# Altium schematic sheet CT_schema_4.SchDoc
size 280 x 211 mm
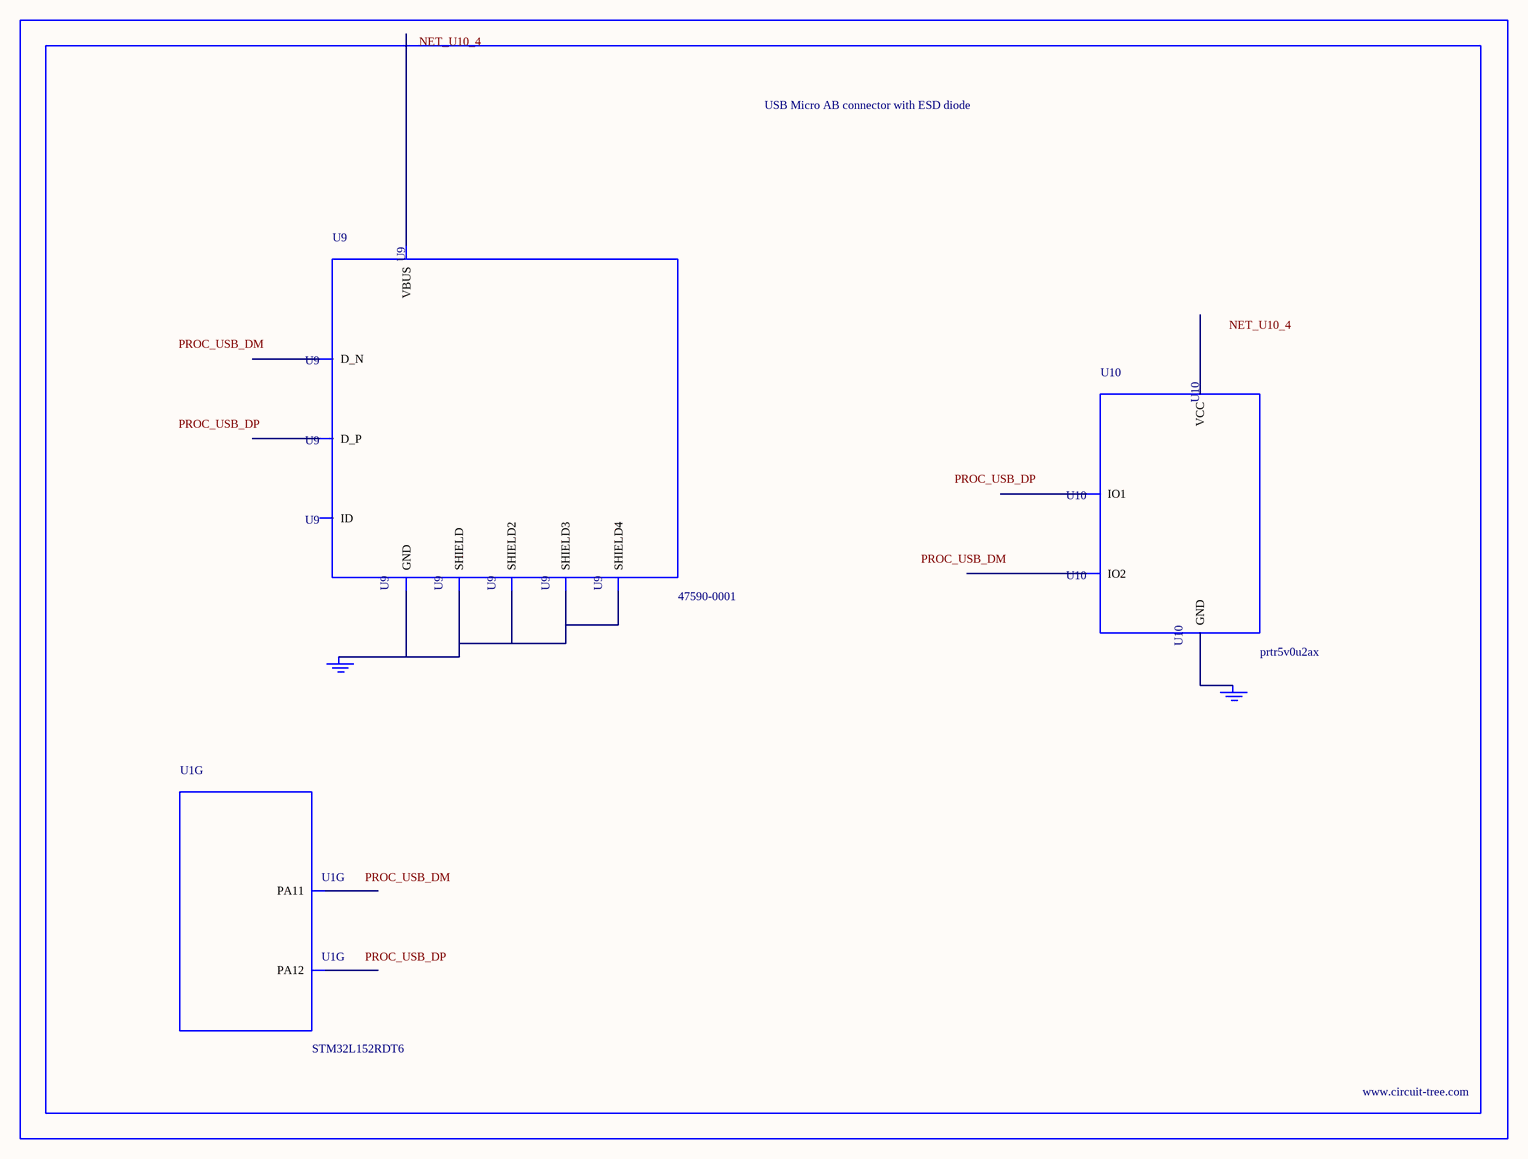
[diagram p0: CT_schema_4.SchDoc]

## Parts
BORDER3  (no value)
GND_INSTANCE_3_0  (no value)
GND_INSTANCE_3_1  (no value)
U1  STM32L152RDT6  [LQFP64]  (part G of 7)
U9  47590-0001  [MICRO_USB_AB]
U10  prtr5v0u2ax  [SOT143B]

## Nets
NetGND_INSTANCE_3_0_0: GND_INSTANCE_3_0.0(GND) U9.5(GND) U9.6(SHIELD) U9.7(SHIELD2) U9.8(SHIELD3) U9.9(SHIELD4)
NetGND_INSTANCE_3_1_0: GND_INSTANCE_3_1.0(GND) U10.1(GND)

Not connected (* = marked no-connect by the designer): U1 44(PA11) 45(PA12); U9 1(VBUS) 2(D_N) 3(D_P) 4(ID); U10 2(IO1) 3(IO2) 4(VCC)

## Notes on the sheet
- Labels drawn without touching a wire or pin: NET_U10_4, PROC_USB_DM, PROC_USB_DP

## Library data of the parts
BORDER3 = BORDER_PAGE3
GND_INSTANCE_3_0 GND_INSTANCE_3_1 = GND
